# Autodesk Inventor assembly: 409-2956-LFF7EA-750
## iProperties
Created: 2010-06
Part Number: 409-2956-LFF7EA-750
Document SubType Name: Weldment
Designer: S. Boerckel
Mass: 6927.17 g
Surface Area: 2787.46 cm^2
Volume: 881.767 cm^3
Density: 7.856 g/cm^3
Description: RECIRCULATION SPOOL
Weld Material: Welded Steel Mild
User Status: WELD
Material: WEDLMENT
SMR: =<MATERIAL>
Author: S. Boerckel
Revision Number: B
Subject: DEMIN WATER FORWARDING PUMP SKID-7EA
